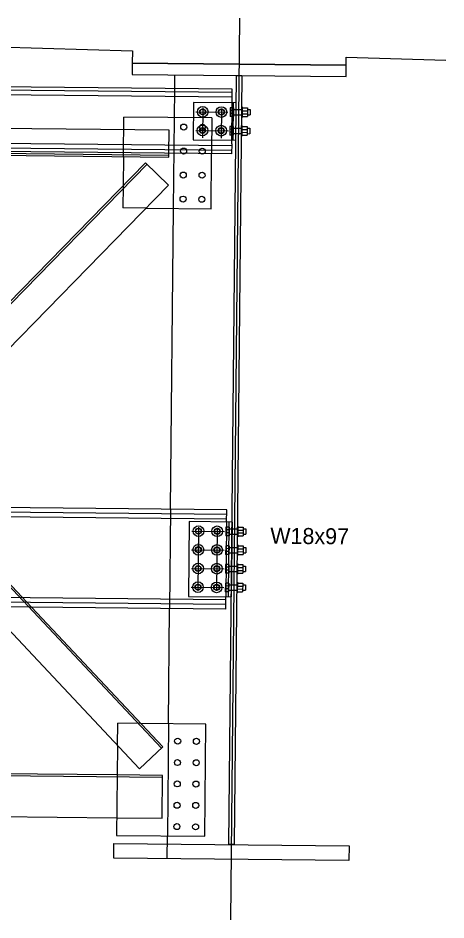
# Model space of a CAD drawing. Extents: x 632312 to 632425, y 378332 to 378413.
# Drawn here: x 632371.24 to 632377.91, y 378382.12 to 378396.19 of the extents above; entities that cross this region are included whole.
import ezdxf

# ---------------------------------------------------------------- set-up
doc = ezdxf.new("R2010")
doc.units = 0
for name, color, linetype in [('B_Boring', 7, 'Continuous'), ('B_Boring Annot', 7, 'Continuous'), ('R_Proposed Const Limits Cut', 7, 'Continuous'), ('R_Shade Removal', 7, 'Continuous'), ('R_Wall', 7, 'Continuous'), ('SHT_Dimensions', 7, 'Continuous')]:
    doc.layers.add(name, color=color, linetype=linetype)

msp = doc.modelspace()

# ---------------------------------------------------------------- linework, layer by layer
at = {"layer": 'B_Boring'}
for p, q in [((632373.684, 378395.094), (632373.686, 378395.308)), ((632374.579, 378395.085), (632363.538, 378395.195)), ((632374.579, 378395.034), (632363.538, 378395.144)), ((632374.578, 378394.897), (632374.579, 378395.085)), ((632373.973, 378394.878), (632373.967, 378394.295)), ((632374.64, 378394.872), (632373.973, 378394.878)), ((632374.592, 378394.289), (632374.598, 378394.872)), ((632374.545, 378394.795), (632374.544, 378394.659)), ((632374.597, 378394.794), (632374.545, 378394.795)), ((632374.597, 378394.749), (632374.545, 378394.749)), ((632374.597, 378394.794), (632374.596, 378394.659)), ((632374.722, 378394.808), (632374.721, 378394.642)), ((632374.722, 378394.808), (632374.733, 378394.808)), ((632374.733, 378394.808), (632374.731, 378394.642)), ((632374.732, 378394.748), (632374.816, 378394.747)), ((632374.733, 378394.793), (632374.816, 378394.792)), ((632374.816, 378394.792), (632374.815, 378394.656)), ((632374.816, 378394.766), (632374.857, 378394.765)), ((632374.857, 378394.765), (632374.857, 378394.682)), ((632372.887, 378394.65), (632372.887, 378394.65)), ((632374.596, 378394.704), (632374.544, 378394.704)), ((632374.596, 378394.659), (632374.544, 378394.659)), ((632374.721, 378394.642), (632374.731, 378394.642)), ((632374.731, 378394.657), (632374.815, 378394.656)), ((632374.732, 378394.702), (632374.815, 378394.702)), ((632374.815, 378394.683), (632374.857, 378394.682)), ((632374.542, 378394.503), (632374.541, 378394.368)), ((632374.594, 378394.502), (632374.542, 378394.503)), ((632374.594, 378394.457), (632374.542, 378394.458)), ((632374.594, 378394.502), (632374.593, 378394.367)), ((632374.72, 378394.517), (632374.718, 378394.35)), ((632374.72, 378394.517), (632374.73, 378394.517)), ((632374.73, 378394.517), (632374.728, 378394.35)), ((632374.729, 378394.456), (632374.813, 378394.455)), ((632374.73, 378394.501), (632374.813, 378394.5)), ((632374.813, 378394.5), (632374.812, 378394.365)), ((632374.813, 378394.474), (632374.855, 378394.474)), ((632374.855, 378394.474), (632374.854, 378394.39)), ((632373.967, 378394.295), (632374.634, 378394.288)), ((632374.594, 378394.412), (632374.541, 378394.413)), ((632374.593, 378394.367), (632374.541, 378394.368)), ((632374.718, 378394.35), (632374.728, 378394.35)), ((632374.728, 378394.366), (632374.812, 378394.365)), ((632374.729, 378394.411), (632374.812, 378394.41)), ((632374.812, 378394.391), (632374.854, 378394.39)), ((632374.569, 378394.077), (632363.528, 378394.186)), ((632374.57, 378394.127), (632363.529, 378394.237)), ((632374.571, 378394.23), (632374.569, 378394.077)), ((632369.048, 378394.071), (632373.59, 378394.026)), ((632373.59, 378394.026), (632373.59, 378394.086)), ((632374.248, 378393.219), (632374.257, 378394.08)), ((632373.238, 378393.229), (632374.248, 378393.219)), ((632373.618, 378388.531), (632373.665, 378393.225)), ((632374.493, 378388.45), (632363.493, 378388.559)), ((632374.493, 378388.522), (632363.494, 378388.632)), ((632374.491, 378388.331), (632374.493, 378388.522)), ((632373.908, 378388.337), (632373.896, 378387.17)), ((632374.575, 378388.33), (632373.908, 378388.337)), ((632374.48, 378388.253), (632374.479, 378388.117)), ((632374.532, 378388.252), (632374.48, 378388.253)), ((632374.521, 378387.164), (632374.533, 378388.33)), ((632374.657, 378388.267), (632374.668, 378388.267)), ((632374.668, 378388.267), (632374.666, 378388.1)), ((632374.668, 378388.251), (632374.751, 378388.25)), ((632374.751, 378388.25), (632374.75, 378388.115)), ((632374.531, 378388.162), (632374.479, 378388.162)), ((632374.531, 378388.117), (632374.479, 378388.117)), ((632374.532, 378388.207), (632374.48, 378388.208)), ((632374.656, 378388.1), (632374.666, 378388.1)), ((632374.666, 378388.115), (632374.75, 378388.115)), ((632374.667, 378388.206), (632374.751, 378388.205)), ((632374.667, 378388.161), (632374.75, 378388.16)), ((632374.75, 378388.141), (632374.792, 378388.14)), ((632374.751, 378388.224), (632374.792, 378388.224)), ((632374.792, 378388.224), (632374.792, 378388.14)), ((632374.477, 378387.961), (632374.476, 378387.826)), ((632374.529, 378387.961), (632374.477, 378387.961)), ((632374.655, 378387.975), (632374.665, 378387.975)), ((632374.665, 378387.975), (632374.663, 378387.808)), ((632374.665, 378387.959), (632374.748, 378387.958)), ((632374.748, 378387.958), (632374.747, 378387.823)), ((632374.528, 378387.87), (632374.476, 378387.871)), ((632374.528, 378387.825), (632374.476, 378387.826)), ((632374.529, 378387.915), (632374.477, 378387.916)), ((632374.663, 378387.824), (632374.747, 378387.823)), ((632374.664, 378387.914), (632374.748, 378387.913)), ((632374.664, 378387.869), (632374.747, 378387.868)), ((632374.747, 378387.849), (632374.789, 378387.849)), ((632374.748, 378387.932), (632374.79, 378387.932)), ((632374.79, 378387.932), (632374.789, 378387.849)), ((632374.652, 378387.683), (632374.662, 378387.683)), ((632374.653, 378387.808), (632374.663, 378387.808)), ((632374.662, 378387.683), (632374.66, 378387.517)), ((632374.474, 378387.669), (632374.473, 378387.534)), ((632374.525, 378387.534), (632374.473, 378387.534)), ((632374.526, 378387.669), (632374.474, 378387.669)), ((632374.526, 378387.624), (632374.474, 378387.624)), ((632374.526, 378387.579), (632374.474, 378387.579)), ((632374.661, 378387.622), (632374.745, 378387.622)), ((632374.661, 378387.577), (632374.744, 378387.576)), ((632374.662, 378387.668), (632374.745, 378387.667)), ((632374.745, 378387.667), (632374.744, 378387.531)), ((632374.744, 378387.557), (632374.786, 378387.557)), ((632374.745, 378387.641), (632374.787, 378387.64)), ((632374.787, 378387.64), (632374.786, 378387.557)), ((632374.649, 378387.392), (632374.659, 378387.392)), ((632374.65, 378387.517), (632374.66, 378387.517)), ((632374.661, 378387.532), (632374.744, 378387.531)), ((632374.472, 378387.378), (632374.47, 378387.242)), ((632374.523, 378387.332), (632374.471, 378387.333)), ((632374.523, 378387.287), (632374.471, 378387.288)), ((632374.524, 378387.377), (632374.472, 378387.378)), ((632374.659, 378387.392), (632374.657, 378387.225)), ((632374.658, 378387.286), (632374.741, 378387.285)), ((632374.659, 378387.376), (632374.742, 378387.375)), ((632374.659, 378387.331), (632374.742, 378387.33)), ((632374.742, 378387.375), (632374.741, 378387.24)), ((632374.741, 378387.266), (632374.783, 378387.265)), ((632374.742, 378387.349), (632374.784, 378387.349)), ((632374.784, 378387.349), (632374.783, 378387.265)), ((632374.479, 378387.045), (632363.479, 378387.154)), ((632373.896, 378387.17), (632374.563, 378387.163)), ((632374.522, 378387.242), (632374.47, 378387.242)), ((632374.478, 378386.973), (632374.48, 378387.164)), ((632374.647, 378387.225), (632374.657, 378387.225)), ((632374.658, 378387.241), (632374.741, 378387.24)), ((632374.478, 378386.973), (632363.478, 378387.082)), ((632373.585, 378385.184), (632373.603, 378386.981)), ((632373.498, 378384.821), (632373.134, 378384.479)), ((632372.785, 378384.384), (632368.952, 378384.422)), ((632368.946, 378383.756), (632372.779, 378383.718)), ((632373.564, 378383.084), (632373.568, 378383.434))]:
    msp.add_line(p, q, dxfattribs=at)
for points in [[(632376.352, 378395.282), (632376.354, 378395.459), (632373.021, 378395.492), (632373.019, 378395.315)], [(632374.608, 378383.299), (632374.525, 378383.299), (632374.644, 378395.299), (632374.727, 378395.298)], [(632376.4, 378383.281), (632376.397, 378383.052), (632372.731, 378383.088), (632372.733, 378383.317)]]:
    msp.add_lwpolyline(points, close=True, dxfattribs=at)
for points in [[(632372.881, 378394.033), (632372.877, 378393.575)], [(632369.808, 378389.717), (632373.585, 378393.585), (632373.228, 378393.934), (632369.803, 378390.428)], [(632373.134, 378384.479), (632370.758, 378387.009)], [(632371.451, 378387.003), (632373.498, 378384.821)], [(632372.79, 378384.845), (632372.776, 378383.442), (632372.776, 378383.442), (632372.776, 378383.442), (632374.151, 378383.428), (632374.168, 378385.178), (632373.154, 378385.188)]]:
    msp.add_lwpolyline(points, dxfattribs=at)
for centre in [(632374.118, 378394.731), (632374.409, 378394.728), (632373.823, 378394.494), (632374.115, 378394.492), (632374.115, 378394.439), (632374.406, 378394.437), (632373.82, 378394.119), (632374.111, 378394.117), (632373.816, 378393.744), (632374.108, 378393.742), (632373.812, 378393.369), (632374.104, 378393.367), (632374.052, 378388.189), (632374.344, 378388.186), (632374.05, 378387.898), (632374.341, 378387.895), (632374.047, 378387.606), (632374.338, 378387.603), (632374.044, 378387.314), (632374.335, 378387.311), (632373.728, 378384.912), (632374.02, 378384.909), (632373.725, 378384.578), (632374.017, 378384.575), (632373.722, 378384.245), (632374.013, 378384.242), (632373.718, 378383.912), (632374.01, 378383.909), (632373.715, 378383.578), (632374.007, 378383.575)]:
    msp.add_circle(centre, 0.0469, dxfattribs=at)
at = {"layer": 'B_Boring Annot'}
for p, q in [((632369.065, 378395.8), (632373.023, 378395.682)), ((632373.023, 378395.682), (632373.021, 378395.492)), ((632376.354, 378395.459), (632376.355, 378395.582)), ((632376.355, 378395.582), (632377.91, 378395.535)), ((632373.021, 378395.492), (632376.354, 378395.459))]:
    msp.add_line(p, q, dxfattribs=at)
at = {"layer": 'R_Proposed Const Limits Cut'}
for p, q in [((632374.578, 378394.96), (632363.537, 378395.07)), ((632373.665, 378393.225), (632373.684, 378395.094)), ((632374.571, 378394.23), (632374.578, 378394.897)), ((632374.597, 378394.768), (632374.722, 378394.767)), ((632372.881, 378394.033), (632372.887, 378394.65)), ((632374.262, 378394.636), (632372.887, 378394.65)), ((632374.262, 378394.636), (632374.257, 378394.08)), ((632374.596, 378394.685), (632374.721, 378394.683)), ((632373.594, 378394.443), (632364.511, 378394.533)), ((632373.59, 378394.086), (632373.594, 378394.443)), ((632374.594, 378394.476), (632374.719, 378394.475)), ((632374.571, 378394.202), (632363.529, 378394.311)), ((632374.593, 378394.393), (632374.718, 378394.392)), ((632373.59, 378394.052), (632364.507, 378394.142)), ((632373.25, 378393.912), (632364.438, 378384.89)), ((632364.844, 378393.996), (632373.475, 378384.8)), ((632372.877, 378393.575), (632372.873, 378393.233)), ((632373.238, 378393.229), (632372.873, 378393.233)), ((632369.982, 378388.567), (632371.451, 378387.003)), ((632373.618, 378388.531), (632373.603, 378386.981)), ((632374.492, 378388.377), (632363.492, 378388.486)), ((632374.491, 378388.331), (632374.48, 378387.164)), ((632374.531, 378388.143), (632374.656, 378388.142)), ((632374.532, 378388.226), (632374.657, 378388.225)), ((632374.528, 378387.851), (632374.653, 378387.85)), ((632374.529, 378387.935), (632374.654, 378387.933)), ((632374.525, 378387.56), (632374.65, 378387.558)), ((632374.526, 378387.643), (632374.651, 378387.642)), ((632374.522, 378387.268), (632374.647, 378387.267)), ((632374.523, 378387.351), (632374.648, 378387.35)), ((632374.479, 378387.118), (632363.48, 378387.228)), ((632372.79, 378384.845), (632372.793, 378385.192)), ((632373.154, 378385.188), (632372.793, 378385.192)), ((632373.585, 378385.184), (632373.568, 378383.434)), ((632373.493, 378384.346), (632364.411, 378384.436)), ((632373.494, 378384.377), (632372.785, 378384.384)), ((632373.487, 378383.711), (632373.494, 378384.377)), ((632372.779, 378383.718), (632373.487, 378383.711))]:
    msp.add_line(p, q, dxfattribs=at)
for centre, radius in [((632374.118, 378394.731), 0.0833), ((632374.118, 378394.731), 0.0417), ((632374.409, 378394.728), 0.0833), ((632374.409, 378394.728), 0.0417), ((632374.115, 378394.439), 0.0833), ((632374.115, 378394.439), 0.0417), ((632374.406, 378394.437), 0.0833), ((632374.406, 378394.437), 0.0417), ((632374.052, 378388.189), 0.0833), ((632374.344, 378388.186), 0.0833), ((632374.052, 378388.189), 0.0417), ((632374.344, 378388.186), 0.0417), ((632374.05, 378387.898), 0.0833), ((632374.341, 378387.895), 0.0833), ((632374.05, 378387.898), 0.0417), ((632374.341, 378387.895), 0.0417), ((632374.047, 378387.606), 0.0833), ((632374.338, 378387.603), 0.0833), ((632374.047, 378387.606), 0.0417), ((632374.338, 378387.603), 0.0417), ((632374.044, 378387.314), 0.0833), ((632374.335, 378387.311), 0.0833), ((632374.044, 378387.314), 0.0417), ((632374.335, 378387.311), 0.0417)]:
    msp.add_circle(centre, radius, dxfattribs=at)
at = {"layer": 'R_Shade Removal'}
msp.add_line((632374.555, 378382.122), (632374.695, 378396.194), dxfattribs=at)
at = {"layer": 'R_Wall'}
for p, q in [((632374.013, 378394.732), (632374.508, 378394.727)), ((632374.118, 378394.792), (632374.113, 378394.327)), ((632374.41, 378394.782), (632374.405, 378394.319)), ((632374.01, 378394.44), (632374.52, 378394.435)), ((632374.053, 378388.25), (632374.043, 378387.256)), ((632374.345, 378388.241), (632374.335, 378387.255)), ((632373.948, 378388.19), (632374.458, 378388.185)), ((632373.945, 378387.899), (632374.455, 378387.894)), ((632373.943, 378387.607), (632374.452, 378387.602)), ((632373.94, 378387.315), (632374.449, 378387.31))]:
    msp.add_line(p, q, dxfattribs=at)
at = {"layer": 'SHT_Dimensions'}
for p, q in [((632374.053, 378388.25), (632374.046, 378387.56)), ((632374.532, 378388.252), (632374.531, 378388.117)), ((632374.575, 378388.33), (632374.563, 378387.163)), ((632374.529, 378387.961), (632374.528, 378387.825)), ((632374.652, 378387.683), (632374.65, 378387.517)), ((632374.526, 378387.669), (632374.525, 378387.534)), ((632374.524, 378387.377), (632374.522, 378387.242))]:
    msp.add_line(p, q, dxfattribs=at)

# ---------------------------------------------------------------- texts
msp.add_text('W18x97', height=0.25, rotation=359.4304, dxfattribs=at).set_placement((632375.171, 378387.993))

doc.saveas('drawing.dxf')
